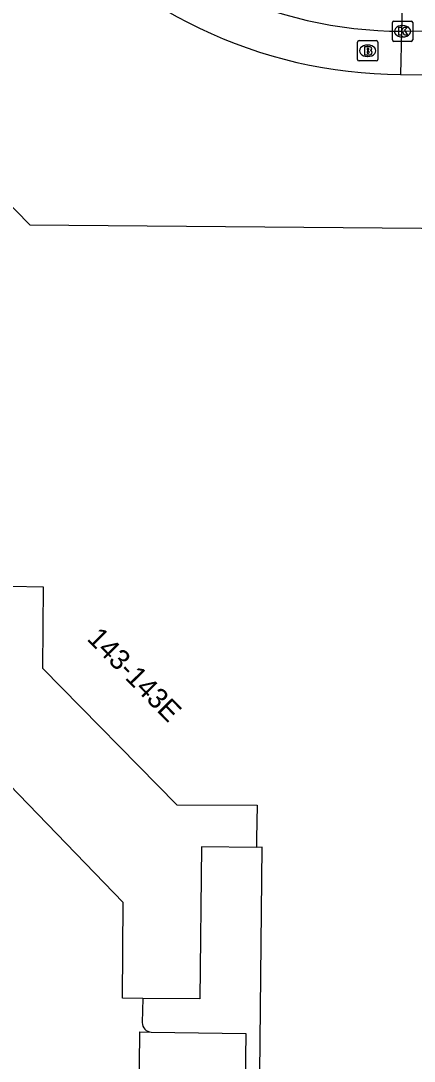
# Model space of a CAD drawing. Extents: x 159265 to 160143, y 383413 to 384319.
# Drawn here: x 159415.8 to 159435.2, y 383581.5 to 383632.7 of the extents above; entities that cross this region are included whole.
import ezdxf

# ---------------------------------------------------------------- set-up
doc = ezdxf.new("R2010")
doc.units = 0
for name, color, linetype in [('IMGEO_Brandkraan', 7, 'Continuous'), ('IMGEO_Erf', 7, 'Continuous'), ('IMGEO_Kolk', 7, 'Continuous'), ('IMGEO_Pand', 7, 'Continuous'), ('IMGEO_Pand_nummerreeks', 7, 'Continuous'), ('IMGEO_Parkeervlak_open', 7, 'Continuous'), ('IMGEO_Rijbaan_lokaal_open', 7, 'Continuous'), ('IMGEO_Voetpad_open', 7, 'Continuous')]:
    doc.layers.add(name, color=color, linetype=linetype)

msp = doc.modelspace()

# ---------------------------------------------------------------- linework, layer by layer
at = {"layer": 'IMGEO_Brandkraan'}
for p, q in [((159432.422, 383630.764), (159432.422, 383631.616)), ((159432.497, 383631.69), (159433.349, 383631.69)), ((159432.91, 383631.47), (159432.935, 383631.47)), ((159433.423, 383631.616), (159433.423, 383630.764)), ((159433.349, 383630.69), (159432.497, 383630.69)), ((159432.933, 383630.91), (159432.908, 383630.91))]:
    msp.add_line(p, q, dxfattribs=at)
for points in [[(159432.422, 383630.764), (159432.422, 383631.616)], [(159432.497, 383631.69), (159433.349, 383631.69)], [(159433.423, 383631.616), (159433.423, 383630.764)], [(159432.77, 383631.39), (159432.77, 383630.99), (159432.983, 383630.99)], [(159433.001, 383631.39), (159432.77, 383631.39)], [(159432.949, 383631.309), (159432.895, 383631.309), (159432.895, 383631.233)], [(159432.895, 383631.233), (159432.948, 383631.233)], [(159432.957, 383631.157), (159432.895, 383631.157), (159432.895, 383631.076)], [(159432.895, 383631.076), (159432.957, 383631.076)], [(159433.349, 383630.69), (159432.497, 383630.69)]]:
    msp.add_lwpolyline(points, dxfattribs=at)
for centre, radius, start, end in [((159432.499, 383631.614), 0.0765, 91.552, 178.448), ((159432.499, 383631.614), 0.0765, 91.552, 178.448), ((159433.347, 383631.614), 0.0765, 1.552, 88.448), ((159433.347, 383631.614), 0.0765, 1.552, 88.448), ((159432.95, 383631.271), 0.0379, 267.8285, 90.9355), ((159432.958, 383631.116), 0.0404, 269.8759, 90.5077), ((159432.989, 383631.241), 0.251, 268.6676, 293.5347), ((159433.005, 383631.245), 0.145, 59.4692, 91.5367), ((159433.03, 383631.292), 0.0922, 285.5137, 58.1501), ((159433.035, 383631.1), 0.105, 301.3115, 78.989), ((159432.499, 383630.766), 0.0765, 181.552, 268.448), ((159432.499, 383630.766), 0.0765, 181.552, 268.448), ((159433.347, 383630.766), 0.0765, 271.552, 358.448), ((159433.347, 383630.766), 0.0765, 271.552, 358.448)]:
    msp.add_arc(centre, radius, start, end, dxfattribs=at)
for centre, major_axis, ratio, start_param, end_param in [((159432.909, 383631.19), (-0.387, 0.002), 0.722429, 4.712389, 7.853982), ((159432.934, 383631.19), (-0.39, 0.002), 0.717154, 1.570796, 4.712389)]:
    msp.add_ellipse(centre, major_axis=major_axis, ratio=ratio, start_param=start_param, end_param=end_param, dxfattribs=at)
at = {"layer": 'IMGEO_Erf'}
msp.add_lwpolyline([(159427.441, 383591.978), (159424.732, 383591.999), (159424.66, 383584.514), (159421.85, 383584.543)], dxfattribs=at)
at = {"layer": 'IMGEO_Kolk'}
for p, q in [((159434.14, 383631.724), (159434.14, 383632.576)), ((159434.215, 383632.65), (159435.067, 383632.65)), ((159435.141, 383632.576), (159435.141, 383631.724)), ((159434.628, 383632.43), (159434.653, 383632.43)), ((159435.067, 383631.65), (159434.215, 383631.65)), ((159434.651, 383631.87), (159434.626, 383631.87))]:
    msp.add_line(p, q, dxfattribs=at)
for points in [[(159434.14, 383631.724), (159434.14, 383632.576)], [(159434.215, 383632.65), (159435.067, 383632.65)], [(159435.141, 383632.576), (159435.141, 383631.724)], [(159434.461, 383632.35), (159434.584, 383632.35), (159434.584, 383632.199), (159434.714, 383632.35), (159434.878, 383632.35), (159434.732, 383632.199), (159434.885, 383631.95), (159434.733, 383631.95), (159434.648, 383632.114), (159434.584, 383632.047), (159434.584, 383631.95), (159434.461, 383631.95), (159434.461, 383632.35)], [(159435.067, 383631.65), (159434.215, 383631.65)]]:
    msp.add_lwpolyline(points, dxfattribs=at)
for centre, start, end in [((159434.217, 383632.574), 91.552, 178.448), ((159434.217, 383632.574), 91.552, 178.448), ((159435.065, 383632.574), 1.552, 88.448), ((159435.065, 383632.574), 1.552, 88.448), ((159434.217, 383631.726), 181.552, 268.448), ((159434.217, 383631.726), 181.552, 268.448), ((159435.065, 383631.726), 271.552, 358.448), ((159435.065, 383631.726), 271.552, 358.448)]:
    msp.add_arc(centre, 0.0765, start, end, dxfattribs=at)
for centre, major_axis, ratio, start_param, end_param in [((159434.627, 383632.15), (-0.387, 0.002), 0.722429, 4.712389, 7.853982), ((159434.652, 383632.15), (-0.39, 0.002), 0.717154, 1.570796, 4.712389)]:
    msp.add_ellipse(centre, major_axis=major_axis, ratio=ratio, start_param=start_param, end_param=end_param, dxfattribs=at)
at = {"layer": 'IMGEO_Pand'}
for points in [[(159404.316, 383637.887), (159407.477, 383640.879), (159413.546, 383634.593), (159410.413, 383631.559), (159410.114, 383631.88), (159409.746, 383631.607), (159408.649, 383630.423), (159416.276, 383622.627), (159441.357, 383622.405), (159441.273, 383618.378), (159441.586, 383618.355)], [(159414.911, 383604.832), (159415.318, 383604.827), (159416.932, 383604.808), (159416.904, 383600.8), (159423.521, 383594.064), (159427.472, 383594.058), (159427.447, 383592.397), (159427.441, 383591.978)], [(159430.462, 383531.615), (159427.108, 383531.63), (159427.729, 383591.98), (159427.441, 383591.978)]]:
    msp.add_lwpolyline(points, dxfattribs=at)
at = {"layer": 'IMGEO_Parkeervlak_open'}
msp.add_lwpolyline([(159422.259, 383582.874), (159426.921, 383582.814), (159426.287, 383535.61), (159421.218, 383535.662)], dxfattribs=at)
at = {"layer": 'IMGEO_Rijbaan_lokaal_open'}
for points in [[(159434.774, 383639.114), (159434.597, 383632.152)], [(159442.612, 383632.061), (159434.637, 383632.152), (159434.597, 383632.152)], [(159421.85, 383584.543), (159420.838, 383584.554), (159420.874, 383589.259), (159414.793, 383595.541)], [(159421.85, 383584.543), (159421.818, 383583.351)], [(159421.218, 383535.662), (159421.705, 383582.889), (159422.259, 383582.874)]]:
    msp.add_lwpolyline(points, dxfattribs=at)
for centre, radius, start, end in [((159434.64, 383653.17), 21.018, 219.0097, 269.8841), ((159422.31, 383583.363), 0.492, 181.4487, 264.0599)]:
    msp.add_arc(centre, radius, start, end, dxfattribs=at)
at = {"layer": 'IMGEO_Voetpad_open'}
for points in [[(159434.597, 383632.152), (159434.543, 383630.026)], [(159434.543, 383630.026), (159441.905, 383629.943)]]:
    msp.add_lwpolyline(points, dxfattribs=at)
msp.add_arc((159434.645, 383653.147), 23.121, 218.9783, 269.7479, dxfattribs=at)

# ---------------------------------------------------------------- texts
at = {"layer": 'IMGEO_Pand_nummerreeks'}
msp.add_text('143-143E', height=1, rotation=314.4894, dxfattribs=at).set_placement((159419.054, 383602.207))

doc.saveas('drawing.dxf')
